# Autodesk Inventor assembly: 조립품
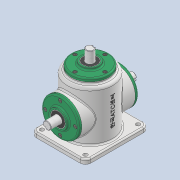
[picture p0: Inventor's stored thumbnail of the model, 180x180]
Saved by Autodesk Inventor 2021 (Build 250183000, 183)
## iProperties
Created: 2021-02
Part Number: 조립품
Document SubType Name: Assembly
Designer: sjtjd
Author: sjtjd
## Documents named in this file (16)
- C:\Users\sjtjd\OneDrive\바탕 화면\710214V1001\조립품.iam
- C:\Users\sjtjd\OneDrive\바탕 화면\710214V1001\본체.ipt
- C:\Users\sjtjd\OneDrive\바탕 화면\710214V1001\커버.ipt
- C:\Users\sjtjd\OneDrive\바탕 화면\710214V1001\베어링 6203.ipt
- C:\Users\sjtjd\OneDrive\바탕 화면\710214V1001\오일 실.ipt
- 오일 실.ipt
- C:\Users\sjtjd\OneDrive\바탕 화면\710214V1001\메인 축.ipt
- 메인 축.ipt
- C:\Users\sjtjd\OneDrive\바탕 화면\710214V1001\키 5x5.ipt
- C:\Users\sjtjd\OneDrive\바탕 화면\710214V1001\메인 베벨기어.ipt
- C:\Users\sjtjd\OneDrive\바탕 화면\710214V1001\서브 축.ipt
- 서브 축.ipt
- C:\Users\sjtjd\OneDrive\바탕 화면\710214V1001\키 4x4.ipt
- C:\Users\sjtjd\OneDrive\바탕 화면\710214V1001\서브 베벨기어.ipt
- C:\Users\sjtjd\OneDrive\바탕 화면\710214V1001\볼트 M4.ipt
- 볼트 M4.ipt
